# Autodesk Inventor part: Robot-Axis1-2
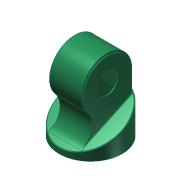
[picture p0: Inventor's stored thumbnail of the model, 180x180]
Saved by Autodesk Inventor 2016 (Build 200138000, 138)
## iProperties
Shininess: 21.0
Length Units: 11269
Angle Units: 11279
Time Units: 11290
Mass Units: 11283
Length Display Precision: 3
Angle Display Precision: 2
Created: 2001-08
Part Number: Robot-Axis1-2
Document SubType Name: ﾓﾃﾞﾘﾝｸﾞ
Designer: Administrator
Density: 1 g/cm^3
Material: Generic
Mass: 193.383 g
Surface Area: 1943.46 cm^2
Volume: 193.383 cm^3
Appearance: Sea Green
Density: 0.0
Volumn: 0.0
Area: 0.0
PropertySet Name: Model Information
Control State: 0
Master: False
Checked Out: False
Author: Administrator
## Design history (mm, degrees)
node "Center-Work Plane"
fillet "Chamfer" dims "d19" = 2
node "Sketch6"
sketch "Sketch7"
  geometry: C1 r 56 at (-128, 0); A1 r 60 centre (-128, 0) between (-128, 60) and (-89.273, -45.828) reference
  constraints: 1 centre point, 1 coincident
  dimensions: "d20" = 4 radial gap between concentric circles of A1 C1
extrude "Extrusion6" join sketch "Sketch7" distance "d21" = 2; taper "d22" = 0 deg
mirror "Mirror3"
shell "Shell1" dims "d25" = 2
sketch "Sketch10"
  geometry: C1 r 75 at (0, 0) reference
hole "Hole1" sketch "Sketch10" at (0, 0) diameter "d26" = 50; stored, may be unused: countersink angle "d30" = 82 deg, drill point angle "d32" = 118 deg; dims "d27" = 6, "d28" = 4, "d29" = 2, "d31" = 2
sketch "Sketch11"
  geometry: C1 r 56 at (0, 0) reference
hole "Hole2" sketch "Sketch11" at (0, 0) diameter "d33" = 50; stored, may be unused: countersink angle "d37" = 82 deg, drill point angle "d39" = 118 deg; dims "d34" = 6, "d35" = 4, "d36" = 2, "d38" = 2
body "Solid1"
sketch "ｽｹｯﾁ1"
  geometry: C1 r 75 at (0, 0)
  constraints: 1 centre point
  dimensions: "d0" = 150 diameter of C1
extrude "Extrusion1" new body sketch "ｽｹｯﾁ1" distance "d1" = 120; taper "d2" = 0 deg
sketch "ｽｹｯﾁ3"
  geometry: L1 (-75, 0)-(-75, 120) reference; L2 (75, 0)-(75, 120) reference; L3 (-75, 0)-(75, 0) reference; L4 (-75, 13)-(75, 82.946)
  constraints: 2 end point, 2 point on line
  dimensions: "d7" = 13 distance from line of L3 L4.start; "d8" = 25 deg angle of L3 L4
extrude "Extrusion3" sketch "ｽｹｯﾁ3" stored distance "d9" = 155; taper "d10" = 0 deg
sketch "Sketch4"
  geometry: L1 (0, 0)-(0, 128); L2 (-60, 128)-(60, 128); L3 (75, 82.946)-(-75, 13) reference; L4 (-75, 0)-(75, 0) reference; L5 (60, 128)-(60, 75.952); L6 (-61.181, 19.444)-(60, 75.952); A1 r 60 centre (0, 128) between (-60, 128) and (60, 128); A2 r 45 centre (-80.199, 60.228) between (-61.181, 19.444) and (-45.828, 89.273); 1 further point
  constraints: 8 end point, 5 point on circle, 4 tangent, 3 point on line, 2 centre point, 2 perpendicular, 1 coincident, 1 midpoint, 1 vertical, 1 other
  dimensions: "d11" = 120 diameter of A1; "d12" = 90 diameter of A2; "d13" = 128 distance between parallel lines of L4 L2
extrude "Extrusion4" join sketch "Sketch4" stored distance "d14" = 76; taper "d15" = 0 deg
